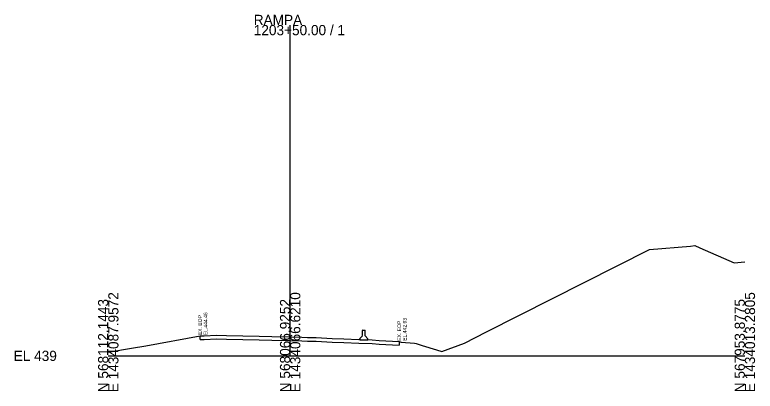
# Model space of a CAD drawing. Extents: x 1431908 to 1449087, y 567604 to 577825.
# Drawn here: x 1431908 to 1432111.5, y 574852.5 to 574955.8 of the extents above; entities that cross this region are included whole.
import ezdxf

# ---------------------------------------------------------------- set-up
doc = ezdxf.new("R2010")
doc.units = 0
for name, color, linetype in [('DESIGN - SHEET - Light Grid', 7, 'Continuous'), ('DESIGN - TYPICAL - Finished Grade and Subgrade', 7, 'Continuous'), ('SURVEY - GROUND - Existing Pavement Layer', 7, 'Continuous'), ('SURVEY - GROUND - Existing Pavement Text', 7, 'Continuous'), ('SURVEY - GROUND - Top of Ground', 7, 'Continuous')]:
    doc.layers.add(name, color=color, linetype=linetype)

msp = doc.modelspace()

# ---------------------------------------------------------------- linework, layer by layer
at = {"layer": 'DESIGN - SHEET - Light Grid'}
for p, q in [((1431983.66, 574862.16), (1431983.66, 574952.98)), ((1431933.66, 574862.16), (1431983.66, 574862.16)), ((1431983.66, 574862.16), (1432108.66, 574862.16))]:
    msp.add_line(p, q, dxfattribs=at)
at = {"layer": 'DESIGN - TYPICAL - Finished Grade and Subgrade'}
for p, q in [((1432003.55, 574867.7), (1432003.57, 574869.15)), ((1432003.67, 574869.25), (1432004.32, 574869.24)), ((1432004.3, 574867.69), (1432004.32, 574869.24)), ((1432002.78, 574866.71), (1432002.78, 574866.82)), ((1432002.81, 574866.88), (1432003.52, 574867.64)), ((1432002.88, 574866.6), (1432004.93, 574866.57)), ((1432005.01, 574866.85), (1432004.32, 574867.62)), ((1432005.03, 574866.67), (1432005.03, 574866.78))]:
    msp.add_line(p, q, dxfattribs=at)
for centre, start, end in [((1432003.45, 574867.7), 316.6261, 359.0732), ((1432003.67, 574869.15), 89.0732, 179.0732), ((1432004.4, 574867.69), 179.0732, 221.5203), ((1432002.88, 574866.82), 136.6261, 179.0732), ((1432002.88, 574866.7), 179.0732, 269.0732), ((1432004.93, 574866.67), 269.0732, 359.0732), ((1432004.93, 574866.78), 359.0732, 41.5203)]:
    msp.add_arc(centre, 0.1, start, end, dxfattribs=at)
at = {"layer": 'SURVEY - GROUND - Existing Pavement Layer'}
for p, q in [((1431958.89, 574866.62), (1431958.89, 574867.62)), ((1431958.89, 574866.62), (1431960.05, 574866.67)), ((1431960.05, 574866.67), (1431963.43, 574866.81)), ((1431963.43, 574866.81), (1431966.16, 574866.76)), ((1431966.16, 574866.76), (1431975.1, 574866.57)), ((1431975.1, 574866.57), (1431978.6, 574866.49)), ((1431978.6, 574866.49), (1431983.66, 574866.37)), ((1431983.66, 574866.37), (1431986.87, 574866.29)), ((1431986.87, 574866.29), (1431988.46, 574866.23)), ((1431988.46, 574866.23), (1431990.84, 574866.17)), ((1431990.84, 574866.17), (1431995.25, 574865.95)), ((1431995.25, 574865.95), (1431998.38, 574865.8)), ((1431998.38, 574865.8), (1432002.58, 574865.65)), ((1432002.58, 574865.65), (1432006.24, 574865.52)), ((1432013.65, 574866.08), (1432013.65, 574865.08)), ((1432006.24, 574865.52), (1432008.17, 574865.4)), ((1432008.17, 574865.4), (1432013.65, 574865.08))]:
    msp.add_line(p, q, dxfattribs=at)
at = {"layer": 'SURVEY - GROUND - Top of Ground'}
msp.add_lwpolyline([(1431933.66, 574863.19), (1431938.39, 574863.98), (1431940.03, 574864.25), (1431943.98, 574864.95), (1431958.89, 574867.62), (1431960.05, 574867.67), (1431963.43, 574867.81), (1431966.16, 574867.76), (1431975.1, 574867.57), (1431978.6, 574867.49), (1431983.66, 574867.37), (1431986.87, 574867.29), (1431988.46, 574867.23), (1431990.84, 574867.17), (1431995.25, 574866.95), (1431998.38, 574866.8), (1432002.58, 574866.65), (1432006.24, 574866.52), (1432008.17, 574866.4), (1432013.65, 574866.08), (1432014.21, 574865.95), (1432017.82, 574865.63), (1432018.31, 574865.58), (1432019.99, 574865.04), (1432023.92, 574863.8), (1432025.38, 574863.34), (1432031.62, 574865.65), (1432037.68, 574868.74), (1432082.45, 574891.4), (1432093.68, 574892.3), (1432094.93, 574892.43), (1432096.26, 574891.85), (1432105.71, 574887.65), (1432108.66, 574887.96)], dxfattribs=at)

# ---------------------------------------------------------------- texts
at = {"layer": 'DESIGN - SHEET - Light Grid'}
for s, p in [('RAMPA', (1431973.66, 574952.98)), ('1203+50.00 / 1', (1431973.66, 574950.18)), ('EL 439', (1431907.66, 574860.76))]:
    msp.add_text(s, height=2.8, dxfattribs=at).set_placement(p)
for s, p in [('E 1434087.9572', (1431936.46, 574852.16)), ('E 1434066.6210', (1431986.46, 574852.16)), ('E 1434013.2805', (1432111.46, 574852.16)), ('N 568112.1443', (1431933.66, 574852.16)), ('N 568066.9252', (1431983.66, 574852.16)), ('N 567953.8775', (1432108.66, 574852.16))]:
    msp.add_text(s, height=2.8, rotation=90, dxfattribs=at).set_placement(p)
at = {"layer": 'SURVEY - GROUND - Existing Pavement Text'}
for s, p in [('EL.444.46', (1431960.9, 574867.82)), ('EX. EOP', (1431959.39, 574867.82)), ('EL.442.93', (1432015.65, 574866.28)), ('EX. EOP', (1432014.15, 574866.28))]:
    msp.add_text(s, height=1, rotation=90, dxfattribs=at).set_placement(p)

doc.saveas('drawing.dxf')
